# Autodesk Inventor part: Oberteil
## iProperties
Created: 2005-01
Part Number: Oberteil
Material: Standard
Document SubType Name: Modeling
Designer: ap
Manufacturer: Standard
Standards Organization: Custom
Author: ap
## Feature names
1. Basis1
